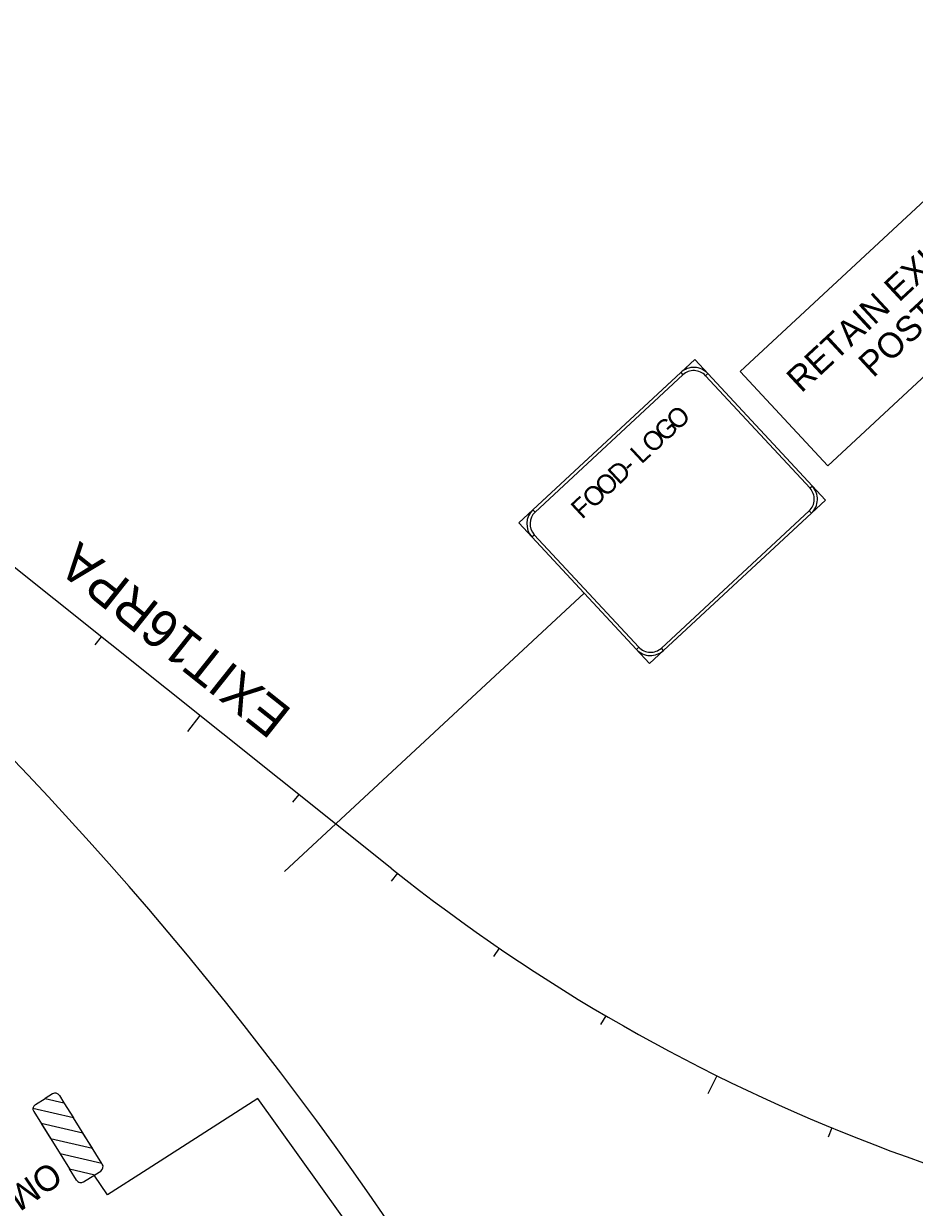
# Model space of a CAD drawing. Extents: x 2001876 to 2025694, y 804561 to 868938.
# Drawn here: x 2022872 to 2023577, y 813699 to 814636 of the extents above; entities that cross this region are included whole.
import ezdxf

# ---------------------------------------------------------------- set-up
doc = ezdxf.new("R2010")
doc.units = 0
for name, color, linetype in [('RD_PD_CLEAR ZONE', 7, 'Continuous'), ('RD_Sketch2', 7, 'Continuous'), ('RD_TX_RoadID', 7, 'Continuous'), ('TR SN EXTRUDED PANEL SIGNS - GROUND MOUNTED', 7, 'Continuous'), ('TR SN FLAT SHEET - TYPE III - FIXED SZ and MSG SIGN', 7, 'Continuous')]:
    doc.layers.add(name, color=color, linetype=linetype)

msp = doc.modelspace()

# ---------------------------------------------------------------- linework, layer by layer
at = {"layer": 'RD_PD_CLEAR ZONE'}
msp.add_line((2023163.12, 813966.82), (2022660.32, 814368.22), dxfattribs=at)
for centre, radius, start, end in [((2020794.27, 812071.86), 2864.79, 355.71297, 56.96135), ((2024056.79, 815086.25), 1432.4, 231.39875, 266.75502)]:
    msp.add_arc(centre, radius, start, end, dxfattribs=at)
at = {"layer": 'RD_Sketch2'}
for p, q in [((2022932.99, 814150.55), (2022927.99, 814144.3)), ((2023011.14, 814088.16), (2023001.15, 814075.66)), ((2023089.29, 814025.77), (2023084.3, 814019.52)), ((2023167.44, 813963.39), (2023162.48, 813957.12)), ((2023247.94, 813904.09), (2023243.42, 813897.48)), ((2023332.37, 813850.54), (2023328.33, 813843.64)), ((2023420.34, 813803.02), (2023413.23, 813788.69)), ((2023511.4, 813761.75), (2023508.35, 813754.35))]:
    msp.add_line(p, q, dxfattribs=at)
at = {"layer": 'TR SN EXTRUDED PANEL SIGNS - GROUND MOUNTED'}
for p, q in [((2023391.68, 814359.79), (2023393.4, 814357.94)), ((2023411.31, 814357.27), (2023413.16, 814359)), ((2023495.91, 814269.9), (2023494.06, 814268.17)), ((2023276.46, 814249.33), (2023274.74, 814251.18)), ((2023493.39, 814250.27), (2023495.12, 814248.42)), ((2023273.94, 814229.7), (2023275.8, 814231.42)), ((2023315.32, 814185.15), (2023078.1, 813964.83)), ((2023358.55, 814142.32), (2023356.69, 814140.6)), ((2023378.17, 814139.81), (2023376.45, 814141.66))]:
    msp.add_line(p, q, dxfattribs=at)
for points in [[(2023438.87, 814360.62), (2023735.38, 814636), (2023804.66, 814561.41), (2023508.14, 814286.03)], [(2023367.04, 814129.46), (2023506.26, 814258.76), (2023402.82, 814370.14), (2023263.6, 814240.84), (2023367.04, 814129.46)], [(2023393.4, 814357.94), (2023276.46, 814249.33), (2023274.74, 814251.18), (2023391.68, 814359.79), (2023393.4, 814357.94)], [(2023494.06, 814268.17), (2023411.31, 814357.27), (2023413.16, 814359), (2023495.91, 814269.9), (2023494.06, 814268.17)], [(2023376.45, 814141.66), (2023493.39, 814250.27), (2023495.12, 814248.42), (2023378.17, 814139.81), (2023376.45, 814141.66)], [(2023275.8, 814231.42), (2023358.55, 814142.32), (2023356.69, 814140.6), (2023273.94, 814229.7), (2023275.8, 814231.42)]]:
    msp.add_lwpolyline(points, close=True, dxfattribs=at)
for points in [[(2023170.56, 813626.06), (2023056.96, 813785.12), (2022969.24, 813728.86)], [(2022969.24, 813728.86), (2022937.87, 813708.74), (2022927.29, 813724.32)]]:
    msp.add_lwpolyline(points, dxfattribs=at)
for centre, radius, start, end in [((2023402.02, 814348.65), 15.2, 42.88379, 132.884), ((2023402.02, 814348.65), 12.67, 42.88379, 132.884), ((2023484.77, 814259.55), 12.67, 312.88385, 42.88406), ((2023484.77, 814259.55), 15.2, 312.88385, 42.88406), ((2023285.08, 814240.04), 15.2, 132.884, 222.88364), ((2023285.08, 814240.04), 12.67, 132.884, 222.88364), ((2023367.83, 814150.94), 15.2, 222.88364, 312.88385), ((2023367.83, 814150.94), 12.67, 222.88364, 312.88385)]:
    msp.add_arc(centre, radius, start, end, dxfattribs=at)
at = {"layer": 'TR SN FLAT SHEET - TYPE III - FIXED SZ and MSG SIGN'}
for p, q in [((2022880.81, 813780.18), (2022888.65, 813785.08)), ((2022894.38, 813788.66), (2022888.65, 813785.08)), ((2022888.65, 813785.08), (2022903.47, 813781.66)), ((2022899.89, 813787.39), (2022903.47, 813781.66)), ((2022910.97, 813769.67), (2022878.94, 813777.06)), ((2022879.54, 813774.67), (2022900.38, 813741.32)), ((2022903.47, 813781.66), (2022910.97, 813769.67)), ((2022933.46, 813733.69), (2022910.97, 813769.67)), ((2022933.46, 813733.69), (2022900.38, 813741.32)), ((2022900.38, 813741.32), (2022907.88, 813729.33)), ((2022913.46, 813720.4), (2022907.88, 813729.33)), ((2022907.88, 813729.33), (2022927.9, 813724.71)), ((2022933.81, 813733.12), (2022933.46, 813733.69)), ((2022918.97, 813719.12), (2022927.9, 813724.71)), ((2022927.9, 813724.71), (2022932.54, 813727.6))]:
    msp.add_line(p, q, dxfattribs=at)
msp.add_lwpolyline([(2022925.96, 813745.68), (2022918.46, 813757.67), (2022885.39, 813765.3), (2022892.89, 813753.31)], close=True, dxfattribs=at)
for centre, start, end in [((2022896.5, 813785.27), 32.00546, 122.00546), ((2022882.93, 813776.79), 176.14981, 212.00546), ((2022882.93, 813776.79), 122.00547, 176.14975), ((2022930.42, 813731), 302.00546, 32.00546), ((2022916.85, 813722.52), 212.00546, 302.00546)]:
    msp.add_arc(centre, 4, start, end, dxfattribs=at)

# ---------------------------------------------------------------- texts
at = {"layer": 'RD_TX_RoadID'}
msp.add_text('EXIT16RPA', height=30, rotation=141.50368, dxfattribs=at).set_placement((2023085.08, 814092.07))
at = {"layer": 'TR SN EXTRUDED PANEL SIGNS - GROUND MOUNTED'}
for s, height, rotation, p in [('RETAIN EXISTING I-BEAM', 20, 42.88379, (2023487.14, 814343.11)), ('POSTS AND SIGN.', 20, 42.88379, (2023544.09, 814355.05)), ('O', 15.2, 42.88379, (2023388.95, 814313.18)), ('G', 15.2, 42.88379, (2023379.38, 814304.29)), ('O', 15.2, 42.88379, (2023369.46, 814295.07)), ('L', 15.2, 42.88379, (2023360.58, 814286.83)), ('D', 15.2, 42.88379, (2023342.83, 814270.34)), ('-', 15.2, 42.88379, (2023352.4, 814279.23)), ('O', 15.2, 42.88379, (2023332.39, 814260.65)), ('F', 15.2, 42.88379, (2023313.6, 814243.19)), ('O', 15.2, 42.88379, (2023322.47, 814251.43)), ('OM 3.5L-24', 20, 214.44263, (2022892.78, 813736.01))]:
    msp.add_text(s, height=height, rotation=rotation, dxfattribs=at).set_placement(p)

doc.saveas('drawing.dxf')
